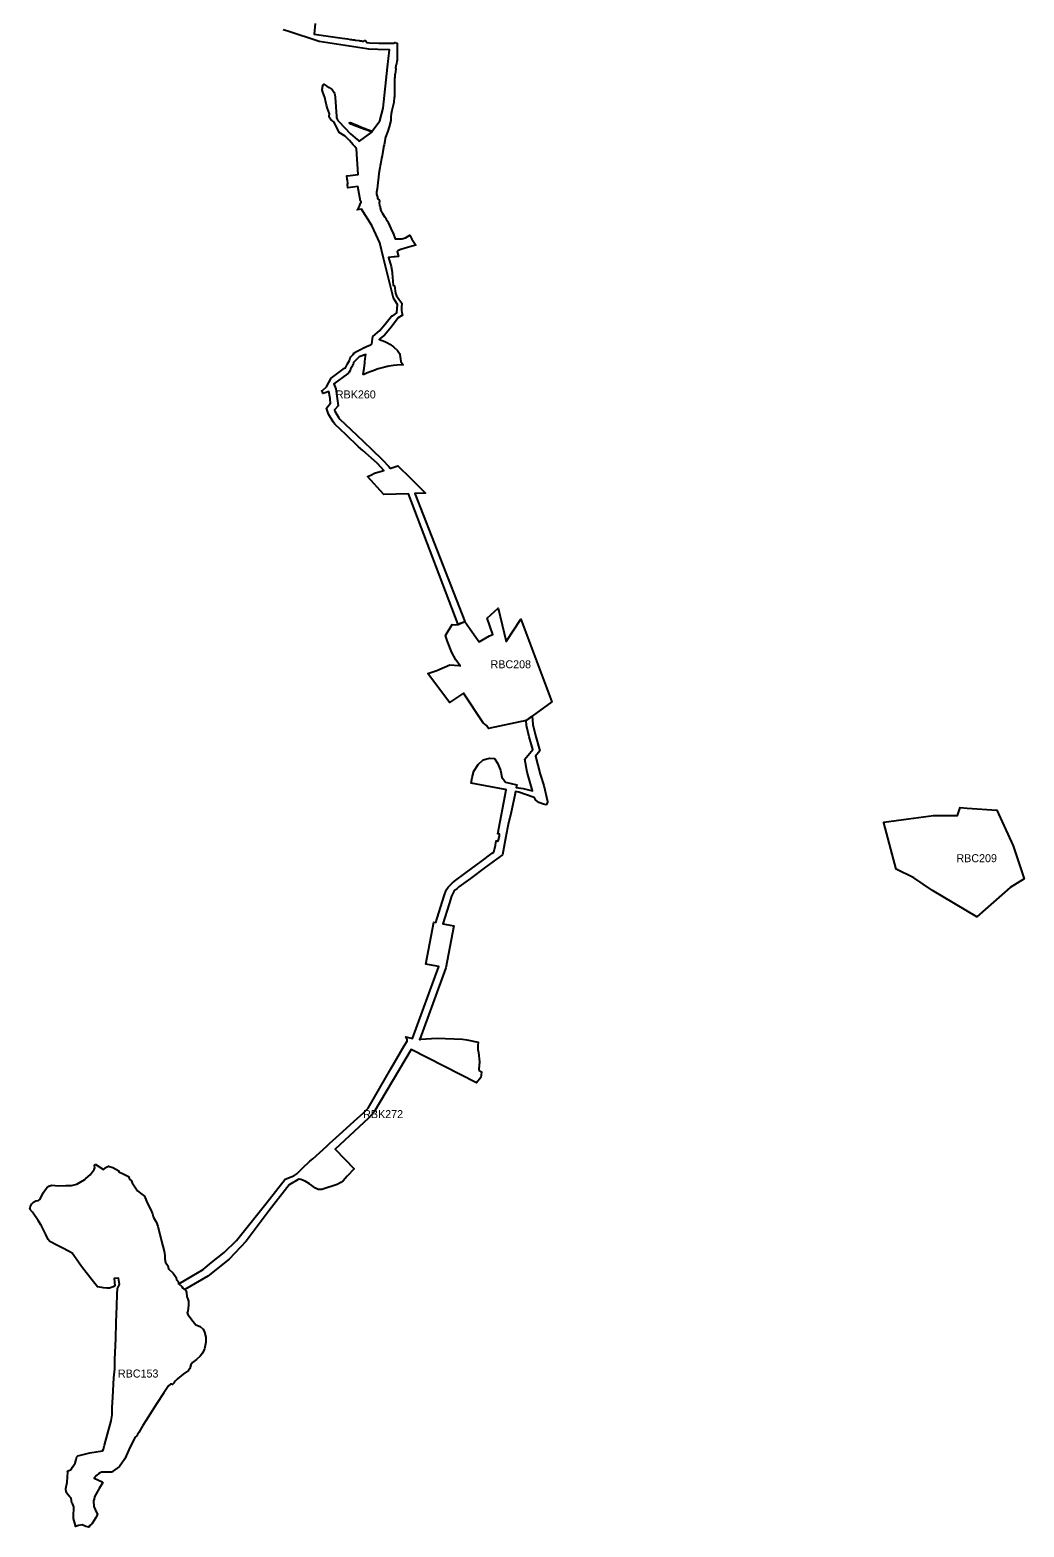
# Model space of a CAD drawing. Extents: x -559776 to -467147, y -1204122 to -1132159.
# Drawn here: x -531461 to -525247, y -1173493 to -1164141 of the extents above; entities that cross this region are included whole.
import ezdxf

# ---------------------------------------------------------------- set-up
doc = ezdxf.new("R2010")
doc.units = 0
doc.layers.add('regionalni_biocentrum_biokoridor', color=7, linetype='Continuous')

msp = doc.modelspace()

# ---------------------------------------------------------------- linework, layer by layer
at = {"layer": 'regionalni_biocentrum_biokoridor'}
msp.add_lwpolyline([(-529676.8, -1164100.5), (-529684, -1164167.39), (-529522.96, -1164190.68), (-529509.4, -1164192.6), (-529475.5, -1164197.5), (-529456.7, -1164200.2), (-529449.6, -1164201), (-529442.8, -1164202.2), (-529435.9, -1164203.1), (-529432.6, -1164204), (-529425.1, -1164204.6), (-529402.2, -1164208), (-529396, -1164208.9), (-529394.6, -1164209.1), (-529391, -1164209.9), (-529387.9, -1164210.2), (-529380.8, -1164211), (-529375.9, -1164211.9), (-529374, -1164212.1), (-529368, -1164208.1), (-529358.9, -1164213.2), (-529355.3, -1164218.7), (-529337.9, -1164221.7), (-529280.4, -1164223.2), (-529208.9, -1164224.2), (-529182.9, -1164224.4), (-529177.9, -1164219.8), (-529175.8, -1164220.4), (-529172.5, -1164221.3), (-529165, -1164223.3), (-529164.8, -1164323.2), (-529165.5, -1164329.7), (-529166.4, -1164336.1), (-529168.9, -1164352.5), (-529172.3, -1164358), (-529175.3, -1164377.9), (-529173.8, -1164384.3), (-529176.47, -1164401.85), (-529178.6, -1164415.8), (-529179.1, -1164418.7), (-529179.8, -1164424.6), (-529180.4, -1164430.5), (-529180.7, -1164436.4), (-529181, -1164442.3), (-529181, -1164445.2), (-529181.7, -1164562), (-529183, -1164562.2), (-529186.1, -1164593.6), (-529198.5, -1164644.7), (-529202.6, -1164665.6), (-529204.4, -1164685.2), (-529205.5, -1164706.4), (-529215.88, -1164747.36), (-529222.7, -1164774.3), (-529238.6, -1164810.7), (-529245.7, -1164858.6), (-529250.3, -1164871.2), (-529249.9, -1164876.8), (-529254.2, -1164900.3), (-529259.4, -1164927.4), (-529262.7, -1164942.1), (-529267.6, -1164969.4), (-529271.8, -1164990.4), (-529274, -1165003), (-529278.9, -1165037.7), (-529281.8, -1165060.8), (-529286.5, -1165097), (-529290.9, -1165133.9), (-529293.4, -1165153.7), (-529294.7, -1165162.6), (-529293.46, -1165167.56), (-529288.8, -1165186.2), (-529288.6, -1165193.7), (-529285.4, -1165195.3), (-529281.9, -1165197.3), (-529279.1, -1165200.2), (-529277.2, -1165203.7), (-529276.4, -1165207.6), (-529275.9, -1165212.7), (-529276.8, -1165218.6), (-529274.6, -1165239.4), (-529271.5, -1165245.1), (-529271.1, -1165248.9), (-529270.8, -1165251.8), (-529269.8, -1165257.7), (-529268.4, -1165263.4), (-529266.6, -1165269.1), (-529264.4, -1165274.6), (-529261.8, -1165279.9), (-529258.8, -1165285.1), (-529257.2, -1165287.6), (-529241.2, -1165310.8), (-529237.5, -1165315.9), (-529233.3, -1165322.6), (-529229.3, -1165329.6), (-529225.6, -1165336.6), (-529222.1, -1165343.8), (-529205.2, -1165381.2), (-529188.8, -1165417.6), (-529176.6, -1165445.4), (-529169.2, -1165445.9), (-529160.2, -1165446.4), (-529135.5, -1165445.2), (-529113, -1165439.1), (-529095.6, -1165429.2), (-529086.9, -1165424.2), (-529072.7, -1165447.5), (-529049.3, -1165485.8), (-529056.6, -1165488), (-529115.3, -1165505.3), (-529142.9, -1165512.7), (-529158.8, -1165519.3), (-529162.5, -1165522.7), (-529165.8, -1165525.7), (-529155.7, -1165556.2), (-529158.5, -1165556.5), (-529178.5, -1165558.7), (-529183.1, -1165559.2), (-529219.7, -1165563.1), (-529203.4, -1165619.4), (-529196.2, -1165654.9), (-529195.8, -1165660.3), (-529190.1, -1165736.3), (-529181, -1165740.1), (-529174.7, -1165785.8), (-529168.4, -1165801.4), (-529162.9, -1165810.6), (-529154, -1165823.2), (-529135.2, -1165848.7), (-529137.4, -1165874.8), (-529138.4, -1165893.8), (-529135.1, -1165907), (-529132.3, -1165923.9), (-529159.8, -1165940.2), (-529201.3, -1165995.2), (-529244, -1166047.4), (-529269.1, -1166066.5), (-529276.7, -1166074.3), (-529276.98, -1166075.83), (-529276, -1166074.6), (-529242.95, -1166087.8), (-529237.6, -1166089.6), (-529234.4, -1166090.7), (-529225.3, -1166095.1), (-529211.3, -1166103.7), (-529189, -1166120.5), (-529164, -1166143), (-529151.2, -1166161.4), (-529148.5, -1166168.9), (-529144.6, -1166198.4), (-529141.9, -1166212.4), (-529130.4, -1166231), (-529129, -1166232), (-529127.3, -1166233.3), (-529168, -1166234.3), (-529188, -1166237.3), (-529216.5, -1166241.6), (-529224.5, -1166242.8), (-529227, -1166243.2), (-529243, -1166247.7), (-529284.2, -1166259.1), (-529321.5, -1166271.9), (-529357.5, -1166286), (-529359, -1166286.7), (-529373.9, -1166293.1), (-529377.4, -1166294.6), (-529375.3, -1166279), (-529372.1, -1166256.3), (-529367.7, -1166221.3), (-529367.1, -1166214.9), (-529364.4, -1166193.5), (-529361.4, -1166168.4), (-529402.4, -1166182.3), (-529429.5, -1166209.9), (-529431.4, -1166212.4), (-529438.1, -1166218.5), (-529441.1, -1166230.3), (-529444, -1166238.4), (-529447.6, -1166245.4), (-529452.2, -1166252.2), (-529453.1, -1166253.8), (-529456.4, -1166261.1), (-529459.8, -1166268.4), (-529465.1, -1166279), (-529469.7, -1166285.1), (-529474.1, -1166288.5), (-529474.87, -1166288.6), (-529560.6, -1166352.9), (-529547.66, -1166383.23), (-529539.29, -1166443.67), (-529534.36, -1166488.44), (-529556.81, -1166513.82), (-529553.98, -1166522.28), (-529529.23, -1166564.14), (-529522.59, -1166572.1), (-529453.76, -1166638.1), (-529375, -1166713.14), (-529324.15, -1166761.8), (-529256, -1166827), (-529217.38, -1166869.32), (-529208.53, -1166879.02), (-529205.48, -1166878.01), (-529161.86, -1166864.19), (-529084.84, -1166939.78), (-528988.19, -1167034.64), (-529053.66, -1167037), (-528742.49, -1167835.86), (-528748.84, -1167839.93), (-528756.42, -1167843.18), (-528759.63, -1167844.87), (-528771.59, -1167849.67), (-528783.54, -1167854.47), (-529094.86, -1167038.48), (-529248, -1167044), (-529349.62, -1166930.29), (-529330.65, -1166921.47), (-529307.57, -1166910.73), (-529270.47, -1166899.22), (-529248.46, -1166892.4), (-529264.14, -1166875.2), (-529290.26, -1166846.54), (-529379.57, -1166768.77), (-529406.06, -1166745.71), (-529484.85, -1166670.63), (-529555.53, -1166602.85), (-529566.11, -1166590.19), (-529595.15, -1166541.07), (-529607.72, -1166503.45), (-529581.27, -1166473.55), (-529584.2, -1166446.93), (-529584.56, -1166443.7), (-529592.78, -1166400.47), (-529614.44, -1166407.94), (-529628.66, -1166411.72), (-529632.54, -1166404.59), (-529637.25, -1166395.95), (-529634.51, -1166394.68), (-529632.23, -1166393.63), (-529606.03, -1166370.95), (-529578.19, -1166316.28), (-529493.8, -1166253.1), (-529488.1, -1166251.3), (-529475.9, -1166226.4), (-529463.9, -1166205.2), (-529459.2, -1166189.5), (-529457.2, -1166187.6), (-529454, -1166184), (-529440.8, -1166168), (-529433.3, -1166159.1), (-529414.8, -1166148.5), (-529401.7, -1166141), (-529389.2, -1166134.4), (-529376.3, -1166127.6), (-529370.9, -1166125), (-529369.9, -1166124.6), (-529360.6, -1166121.2), (-529352.4, -1166117.5), (-529336.7, -1166110.7), (-529335.4, -1166110.1), (-529331.8, -1166108.8), (-529330.7, -1166108.3), (-529323.25, -1166103.04), (-529316.2, -1166056.2), (-529302.1, -1166043.4), (-529272.4, -1166019), (-529232.8, -1165970.5), (-529201.1, -1165929), (-529199.4, -1165927.9), (-529192.9, -1165927.7), (-529166.41, -1165908.49), (-529162.5, -1165855.7), (-529188, -1165817.7), (-529249.8, -1165566.3), (-529273.1, -1165471.7), (-529323.7, -1165363.3), (-529387.3, -1165260.7), (-529403.3, -1165263.3), (-529415.2, -1165265.8), (-529409.7, -1165259.2), (-529406.6, -1165255), (-529404, -1165250.4), (-529403.1, -1165247.9), (-529396.5, -1165230.3), (-529393.4, -1165223.1), (-529389.38, -1165216.38), (-529393.4, -1165210), (-529411.2, -1165118.8), (-529472.8, -1165128.3), (-529474.7, -1165105.9), (-529472.8, -1165099.7), (-529474.6, -1165079.7), (-529477.6, -1165073.9), (-529479.5, -1165052.4), (-529457.9, -1165050.1), (-529409.5, -1165045), (-529420.2, -1164883.7), (-529430.3, -1164868.5), (-529440.7, -1164857.9), (-529463, -1164832.1), (-529491, -1164804.5), (-529528.6, -1164781.5), (-529545.1, -1164746.5), (-529561.6, -1164714.6), (-529573.11, -1164707.64), (-529578.3, -1164704.5), (-529589.1, -1164685.2), (-529590.5, -1164679.4), (-529588.9, -1164665.8), (-529599.7, -1164632.3), (-529606.3, -1164610.7), (-529610.4, -1164591.8), (-529617.3, -1164564), (-529622.8, -1164546.3), (-529629.5, -1164529.8), (-529634, -1164515.3), (-529633.2, -1164511.1), (-529632.3, -1164506.5), (-529631.4, -1164501.8), (-529631.1, -1164499.5), (-529628.6, -1164483.4), (-529623, -1164480.8), (-529603.96, -1164491.85), (-529589.9, -1164500.6), (-529577.6, -1164509.2), (-529571.7, -1164513.6), (-529566.5, -1164518.9), (-529562.2, -1164524.9), (-529558.9, -1164531.5), (-529556.6, -1164538.5), (-529555.5, -1164545.8), (-529553.6, -1164560.7), (-529544.3, -1164681.1), (-529544.2, -1164683.6), (-529543.3, -1164688.6), (-529541.9, -1164693.4), (-529540.1, -1164698.1), (-529537.8, -1164702.6), (-529535.2, -1164706.9), (-529532.1, -1164710.9), (-529530.3, -1164712.7), (-529456.3, -1164791), (-529427.5, -1164816.1), (-529405, -1164833), (-529400, -1164836.6), (-529324, -1164780.1), (-529359, -1164765.6), (-529368.1, -1164762.3), (-529417.4, -1164744), (-529434.8, -1164737.8), (-529455, -1164730.6), (-529457.9, -1164729.1), (-529460.9, -1164727.6), (-529464.4, -1164721.2), (-529458.8, -1164719.2), (-529450.7, -1164722.1), (-529434.4, -1164728.9), (-529431.6, -1164730.1), (-529415.2, -1164736.9), (-529383.2, -1164750.3), (-529366.1, -1164757.4), (-529360.6, -1164759.8), (-529357.5, -1164761.1), (-529332.4, -1164769.4), (-529328.1, -1164770.9), (-529321.6, -1164773.1), (-529273.1, -1164709.9), (-529253, -1164629.4), (-529225.51, -1164373.73), (-529213.84, -1164265.21), (-529286.68, -1164262.56), (-529341.9, -1164261.6), (-529354.14, -1164259.68), (-529653.1, -1164212.8), (-529848.43, -1164149.26), (-529876.9, -1164140)], dxfattribs=at)
for points in [[(-528320.72, -1168427.01), (-528359, -1168455), (-528593.78, -1168504.73), (-528607, -1168487), (-528628, -1168470), (-528751, -1168284), (-528837, -1168342), (-528973, -1168162), (-528918, -1168143), (-528836.07, -1168107.91), (-528780.12, -1168111.16), (-528770.34, -1168112.52), (-528797.65, -1168076.18), (-528822.76, -1168030.11), (-528850, -1167961), (-528862, -1167925), (-528821, -1167856), (-528797.82, -1167857.49), (-528783.54, -1167854.47), (-528771.59, -1167849.67), (-528759.63, -1167844.87), (-528756.42, -1167843.18), (-528748.84, -1167839.93), (-528742.49, -1167835.86), (-528683.9, -1167919.94), (-528653, -1167964), (-528588.53, -1167927.02), (-528567, -1167918), (-528603, -1167816), (-528533, -1167753), (-528484, -1167961), (-528392, -1167823), (-528199, -1168338)], [(-530492.91, -1172009.69), (-530504.32, -1172002.1), (-530509.66, -1171992.88), (-530530.33, -1171974.12), (-530447.66, -1171926.77), (-530377.72, -1171884.9), (-530325.6, -1171840.88), (-530246.66, -1171779.2), (-530168.88, -1171702.71), (-529986.33, -1171474.44), (-529864.21, -1171319.49), (-529826.95, -1171305.48), (-529810.5, -1171299.95), (-529793.21, -1171287.61), (-529756.08, -1171251.86), (-529710.22, -1171208.42), (-529692.5, -1171192.96), (-529649.2, -1171153.86), (-529604.88, -1171113.36), (-529587.08, -1171097.94), (-529587.24, -1171097.77), (-529504.74, -1171022.79), (-529432.95, -1170958.53), (-529377.95, -1170907.92), (-529347.31, -1170876.08), (-529204.74, -1170631.42), (-529120.86, -1170488.13), (-529102.37, -1170457.23), (-529101.98, -1170447), (-529110.24, -1170432.04), (-529070.24, -1170440.84), (-528905.34, -1169991.65), (-528985.66, -1169976.53), (-528936.31, -1169714.43), (-528923.45, -1169716.85), (-528884.32, -1169590.73), (-528867.9, -1169537.8), (-528860.74, -1169520.76), (-528854.11, -1169508.74), (-528846.49, -1169496.96), (-528836.43, -1169484.95), (-528820.71, -1169470.13), (-528807.69, -1169458.85), (-528733.38, -1169404.88), (-528639.4, -1169335.13), (-528570.39, -1169284.13), (-528559.91, -1169276.54), (-528558.51, -1169269), (-528551.24, -1169233.58), (-528546.61, -1169206.43), (-528544.25, -1169207.3), (-528538.02, -1169208.02), (-528534.55, -1169205.71), (-528532.09, -1169199.93), (-528526.44, -1169178.25), (-528525.57, -1169165.53), (-528530.64, -1169162.21), (-528536.6, -1169162.2), (-528484.04, -1168887.19), (-528490, -1168886), (-528703, -1168846), (-528697, -1168812), (-528686, -1168771), (-528658, -1168729), (-528627, -1168701), (-528587, -1168691), (-528557, -1168692), (-528538, -1168721), (-528519, -1168765), (-528511, -1168808), (-528488, -1168841), (-528418, -1168857), (-528420.67, -1168873.05), (-528378.08, -1168879.26), (-528318.72, -1168895.16), (-528352.02, -1168778.05), (-528366.5, -1168695.64), (-528318, -1168636), (-528339, -1168558), (-528357, -1168486), (-528359, -1168455), (-528320.72, -1168427.01), (-528317.32, -1168479.81), (-528300.28, -1168547.95), (-528274.06, -1168645.36), (-528301.06, -1168678.56), (-528270.94, -1168791.06), (-528247.77, -1168861.91), (-528224.6, -1168960.22), (-528224.42, -1168966.9), (-528232.75, -1168981), (-528251.21, -1168977.38), (-528278.72, -1168966.53), (-528298.63, -1168953.16), (-528306.23, -1168939.06), (-528315.64, -1168934.72), (-528404.87, -1168903.29), (-528425, -1168899), (-528428.92, -1168920.59), (-528452.92, -1169027.92), (-528471.97, -1169104.5), (-528485.42, -1169179.67), (-528507.09, -1169293.86), (-528543.83, -1169320.45), (-528612.62, -1169371.29), (-528706.75, -1169441.16), (-528779.68, -1169494.12), (-528790.52, -1169503.52), (-528803.63, -1169515.87), (-528810.22, -1169523.73), (-528815.47, -1169531.85), (-528820.18, -1169540.4), (-528825.57, -1169553.22), (-528840.3, -1169600.72), (-528878.93, -1169725.23), (-528811.16, -1169737.99), (-528860.51, -1170000.1), (-529024, -1170445), (-529025, -1170445), (-529026, -1170447), (-529025, -1170447), (-529024, -1170447), (-529023, -1170447), (-529019, -1170446), (-528914.14, -1170439.76), (-528757.35, -1170444.87), (-528729.44, -1170450.42), (-528658.59, -1170464.63), (-528658.36, -1170464.68), (-528661.29, -1170485.2), (-528660.7, -1170510.99), (-528657.58, -1170529.37), (-528649.91, -1170587.23), (-528654.64, -1170633.17), (-528652.28, -1170641.83), (-528638.75, -1170650.02), (-528638.88, -1170651.49), (-528642.66, -1170685.81), (-528669.21, -1170719.07), (-529077.25, -1170510.43), (-529309.37, -1170899.74), (-529344.1, -1170939.75), (-529553.28, -1171133.33), (-529434.05, -1171256), (-529477.29, -1171301.67), (-529490.66, -1171315.62), (-529502.86, -1171331.19), (-529517.35, -1171340.95), (-529540.2, -1171352.8), (-529636.82, -1171384.16), (-529658.21, -1171384.99), (-529676.47, -1171376.63), (-529713.53, -1171349.71), (-529739.1, -1171332.59), (-529768.08, -1171322.55), (-529777.14, -1171320.04), (-529780, -1171321), (-529781, -1171322), (-529783, -1171323), (-529839.29, -1171354.67), (-529965.8, -1171514.95), (-530109.5, -1171707.15), (-530215.3, -1171820.15), (-530349.35, -1171926.55)], [(-525601.6, -1169002.3), (-525416, -1169015), (-525314, -1169238), (-525246.57, -1169443.91), (-525333, -1169499), (-525542, -1169681), (-525820, -1169516), (-525936, -1169438), (-526046, -1169383), (-526062.62, -1169321.63), (-526115.8, -1169125.26), (-526124, -1169095), (-526124, -1169091), (-525970.01, -1169069.71), (-525813, -1169048), (-525770.47, -1169047.91), (-525694.83, -1169047.75), (-525662, -1169049), (-525645.12, -1168999.32)], [(-531052.64, -1171227.3), (-531000.5, -1171260.63), (-530982.25, -1171244.48), (-530968.7, -1171239.28), (-530941.59, -1171246.57), (-530905.61, -1171267.92), (-530904.57, -1171274.17), (-530878.5, -1171287.71), (-530844.61, -1171304.37), (-530837.84, -1171319.99), (-530825.32, -1171330.93), (-530820.76, -1171343.14), (-530788.71, -1171394.07), (-530769.29, -1171407.66), (-530745, -1171425.6), (-530727.23, -1171467.17), (-530703.92, -1171511.31), (-530693.72, -1171536.05), (-530690.32, -1171552.54), (-530686.43, -1171563.7), (-530670.89, -1171586.01), (-530660.21, -1171613.9), (-530638.84, -1171708.01), (-530621.36, -1171770.92), (-530617.47, -1171796.63), (-530616.99, -1171817.97), (-530613.59, -1171841.25), (-530597.56, -1171859.2), (-530593.68, -1171880.06), (-530565.02, -1171907.03), (-530547.06, -1171934.67), (-530545.11, -1171949.71), (-530536.86, -1171956.5), (-530533.46, -1171962.32), (-530531.03, -1171973.48), (-530530.33, -1171974.12), (-530509.66, -1171992.88), (-530504.32, -1172002.1), (-530492.91, -1172009.69), (-530485.38, -1172014.71), (-530481.98, -1172027.32), (-530479.55, -1172055.94), (-530476.64, -1172062.73), (-530468.38, -1172081.65), (-530470.32, -1172108.08), (-530473.24, -1172144.46), (-530477.12, -1172152.22), (-530476.64, -1172159.5), (-530472.75, -1172165.32), (-530440.7, -1172208.98), (-530423.7, -1172229.35), (-530396.02, -1172241.48), (-530377.08, -1172257.97), (-530368.34, -1172276.4), (-530361.54, -1172306.28), (-530360.08, -1172338.78), (-530369.8, -1172379.52), (-530381.94, -1172406.69), (-530395.54, -1172425.12), (-530419.82, -1172446.95), (-530444.1, -1172465.86), (-530453.81, -1172480.9), (-530460.61, -1172503.7), (-530469.7, -1172515.58), (-530503.2, -1172538.87), (-530537.68, -1172568.45), (-530553.23, -1172582.52), (-530561.48, -1172594.16), (-530569.74, -1172601.92), (-530575.56, -1172601.44), (-530580.91, -1172601.44), (-530594.5, -1172610.17), (-530624.13, -1172654.8), (-530666.72, -1172722.07), (-530736.17, -1172830), (-530755.59, -1172858.62), (-530780.36, -1172901.79), (-530787.16, -1172915.85), (-530792.01, -1172923.13), (-530801.73, -1172932.35), (-530833.78, -1172992.01), (-530867.77, -1173066.51), (-530901.28, -1173115.99), (-530943.63, -1173147.03), (-530946.93, -1173149.46), (-530988.7, -1173150.92), (-531013.47, -1173151.4), (-531029.01, -1173159.65), (-531043.87, -1173171.77), (-531058.44, -1173187.78), (-531009.08, -1173210.92), (-531003.9, -1173214.61), (-531028.01, -1173252.01), (-531046.86, -1173286.3), (-531056.53, -1173304.17), (-531059.95, -1173318.66), (-531062.34, -1173328.8), (-531060.89, -1173364.05), (-531052.67, -1173384.72), (-531037.19, -1173415.15), (-531051.22, -1173438.33), (-531072.01, -1173470.21), (-531074.21, -1173472.65), (-531085.06, -1173484.7), (-531093.28, -1173493.39), (-531110.21, -1173489.04), (-531134.87, -1173479.87), (-531157.03, -1173484.49), (-531174.72, -1173489.43), (-531174.67, -1173484.59), (-531188.05, -1173439.78), (-531189.02, -1173418.05), (-531185.64, -1173380.38), (-531186.6, -1173367.34), (-531194.34, -1173347.05), (-531198.21, -1173341.74), (-531203.53, -1173312.28), (-531213.2, -1173302.14), (-531226.25, -1173288.13), (-531233.99, -1173275.09), (-531235.44, -1173252.88), (-531227.22, -1173212.31), (-531224.71, -1173180.53), (-531224.04, -1173151.4), (-531225.01, -1173144.12), (-531203.64, -1173132.97), (-531193.45, -1173119.39), (-531178.39, -1173094.65), (-531171.59, -1173072.34), (-531167.22, -1173054.39), (-531161.88, -1173049.05), (-531126.91, -1173040.32), (-531087.09, -1173029.16), (-531046.49, -1173023.1), (-531006.67, -1173017.28), (-531000.35, -1173007.09), (-530994.04, -1172981.39), (-530976.56, -1172913.48), (-530952.28, -1172829.32), (-530945.48, -1172792.46), (-530945.48, -1172745.89), (-530942.08, -1172681.38), (-530936.74, -1172560.4), (-530929.94, -1172504.62), (-530930.42, -1172446.41), (-530924.11, -1172315.25), (-530921.68, -1172215.33), (-530916.82, -1172114.23), (-530914.76, -1172038.82), (-530913.79, -1172002.21), (-530902.38, -1171982.09), (-530900.92, -1171976.02), (-530907.72, -1171937.96), (-530934.67, -1171941.35), (-530930.54, -1171987.42), (-530940.01, -1171992.27), (-530963.08, -1172000.51), (-530979.59, -1172000.51), (-530999.62, -1171998.82), (-531038.46, -1171992.52), (-531071.97, -1171950.81), (-531137.76, -1171866.65), (-531172.24, -1171817.67), (-531196.52, -1171781.78), (-531251.39, -1171754.3), (-531287.33, -1171735.39), (-531336.37, -1171710.17), (-531346.57, -1171698.05), (-531362.11, -1171666.53), (-531387.36, -1171612.23), (-531391.33, -1171606.1), (-531409.69, -1171577.8), (-531444.65, -1171526.41), (-531460.53, -1171508.21), (-531459.6, -1171502.29), (-531457.41, -1171489.2), (-531449.62, -1171474.55), (-531438.07, -1171463.33), (-531423.09, -1171455.85), (-531406.87, -1171454.29), (-531396.88, -1171445.26), (-531377.54, -1171404.74), (-531363.19, -1171384.95), (-531355.39, -1171373.42), (-531342.31, -1171363.29), (-531324.59, -1171358.6), (-531282.88, -1171361.21), (-531237, -1171359.65), (-531199.98, -1171359.65), (-531168.18, -1171350.8), (-531117.08, -1171322.68), (-531110.17, -1171316.74), (-531083.19, -1171293.53), (-531059.73, -1171259.17), (-531055.77, -1171248.65), (-531057.85, -1171237.71)]]:
    msp.add_lwpolyline(points, close=True, dxfattribs=at)

# ---------------------------------------------------------------- texts
for s, p in [('RBK260', (-529548.11, -1166443.08)), ('RBC208', (-528581.19, -1168128.87)), ('RBC209', (-525669.07, -1169340.16)), ('RBK272', (-529377.38, -1170938.93)), ('RBC153', (-530910.3, -1172559.33))]:
    msp.add_text(s, height=50, dxfattribs=at).set_placement(p)

doc.saveas('drawing.dxf')
